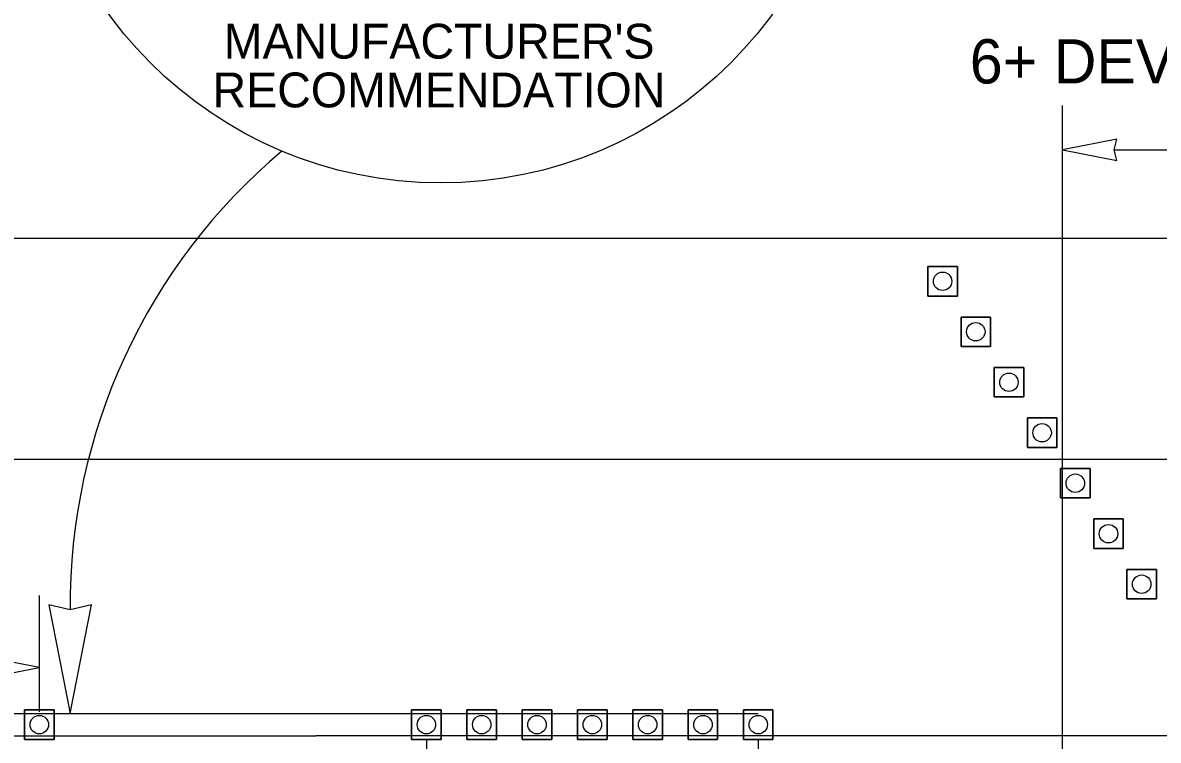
# Model space of a CAD drawing. Extents: x 99999.1 to 100095.7, y 99995 to 100010.7.
# Drawn here: x 100042.947 to 100045, y 100006.584 to 100007.882 of the extents above; entities that cross this region are included whole.
import ezdxf

# ---------------------------------------------------------------- set-up
doc = ezdxf.new("R2010")
doc.units = 0
for name, color, linetype in [('RD_ED_ShoulderPavedEdge', 7, 'Continuous'), ('RD_MK_LineDblYellowCenter', 7, 'Continuous'), ('RD_MK_LineEdgeWhite', 7, 'Continuous'), ('RD_MK_LineNoPass', 7, 'Continuous'), ('RD_MK_LineSkipCenter', 7, 'Continuous'), ('TR_WZ_TrafficCone', 7, 'Continuous'), ('TR_WZ_WorkZoneDetails', 7, 'Continuous'), ('TR_WZ_WorkZoneTextCurrent', 7, 'Continuous')]:
    doc.layers.add(name, color=color, linetype=linetype)

msp = doc.modelspace()

# ---------------------------------------------------------------- linework, layer by layer
at = {"layer": 'RD_ED_ShoulderPavedEdge'}
msp.add_line((100040.1076, 100007.4923), (100055.6424, 100007.4923), dxfattribs=at)
at = {"layer": 'RD_MK_LineDblYellowCenter'}
for p, q in [((100040.1282, 100006.6323), (100043.4767, 100006.6323)), ((100040.0869, 100006.5923), (100043.4767, 100006.5923))]:
    msp.add_line(p, q, dxfattribs=at)
at = {"layer": 'RD_MK_LineEdgeWhite'}
msp.add_line((100040.1076, 100007.0923), (100055.6424, 100007.0923), dxfattribs=at)
at = {"layer": 'RD_MK_LineNoPass'}
msp.add_line((100043.4767, 100006.6323), (100044.2767, 100006.6323), dxfattribs=at)
at = {"layer": 'RD_MK_LineSkipCenter'}
msp.add_lwpolyline([(100051.15, 100006.5923), (100043.4767, 100006.5923)], dxfattribs=at)
at = {"layer": 'TR_WZ_TrafficCone'}
for points in [[(100044.6367, 100007.4411), (100044.5834, 100007.4411), (100044.5834, 100007.3877), (100044.6367, 100007.3877), (100044.6367, 100007.4411)], [(100044.6367, 100007.3877), (100044.5834, 100007.3877), (100044.5834, 100007.4411), (100044.6367, 100007.4411), (100044.6367, 100007.3877)], [(100044.6967, 100007.3497), (100044.6434, 100007.3497), (100044.6434, 100007.2964), (100044.6967, 100007.2964), (100044.6967, 100007.3497)], [(100044.6967, 100007.2964), (100044.6434, 100007.2964), (100044.6434, 100007.3497), (100044.6967, 100007.3497), (100044.6967, 100007.2964)], [(100044.7567, 100007.2584), (100044.7034, 100007.2584), (100044.7034, 100007.2051), (100044.7567, 100007.2051), (100044.7567, 100007.2584)], [(100044.7567, 100007.2051), (100044.7034, 100007.2051), (100044.7034, 100007.2584), (100044.7567, 100007.2584), (100044.7567, 100007.2051)], [(100044.8167, 100007.1671), (100044.7634, 100007.1671), (100044.7634, 100007.1137), (100044.8167, 100007.1137), (100044.8167, 100007.1671)], [(100044.8167, 100007.1137), (100044.7634, 100007.1137), (100044.7634, 100007.1671), (100044.8167, 100007.1671), (100044.8167, 100007.1137)], [(100044.8234, 100007.0757), (100044.8767, 100007.0757), (100044.8767, 100007.0224), (100044.8234, 100007.0224), (100044.8234, 100007.0757)], [(100044.8234, 100007.0224), (100044.8767, 100007.0224), (100044.8767, 100007.0757), (100044.8234, 100007.0757), (100044.8234, 100007.0224)], [(100044.8834, 100006.9844), (100044.9367, 100006.9844), (100044.9367, 100006.9311), (100044.8834, 100006.9311), (100044.8834, 100006.9844)], [(100044.8834, 100006.9311), (100044.9367, 100006.9311), (100044.9367, 100006.9844), (100044.8834, 100006.9844), (100044.8834, 100006.9311)], [(100044.9434, 100006.8931), (100044.9967, 100006.8931), (100044.9967, 100006.8397), (100044.9434, 100006.8397), (100044.9434, 100006.8931)], [(100044.9434, 100006.8397), (100044.9967, 100006.8397), (100044.9967, 100006.8931), (100044.9434, 100006.8931), (100044.9434, 100006.8397)], [(100043.0033, 100006.639), (100042.95, 100006.639), (100042.95, 100006.5857), (100043.0033, 100006.5857), (100043.0033, 100006.639)], [(100043.0033, 100006.5857), (100042.95, 100006.5857), (100042.95, 100006.639), (100043.0033, 100006.639), (100043.0033, 100006.5857)], [(100043.7033, 100006.639), (100043.65, 100006.639), (100043.65, 100006.5857), (100043.7033, 100006.5857), (100043.7033, 100006.639)], [(100043.7033, 100006.5857), (100043.65, 100006.5857), (100043.65, 100006.639), (100043.7033, 100006.639), (100043.7033, 100006.5857)], [(100043.8033, 100006.639), (100043.75, 100006.639), (100043.75, 100006.5857), (100043.8033, 100006.5857), (100043.8033, 100006.639)], [(100043.8033, 100006.5857), (100043.75, 100006.5857), (100043.75, 100006.639), (100043.8033, 100006.639), (100043.8033, 100006.5857)], [(100043.9033, 100006.639), (100043.85, 100006.639), (100043.85, 100006.5857), (100043.9033, 100006.5857), (100043.9033, 100006.639)], [(100043.9033, 100006.5857), (100043.85, 100006.5857), (100043.85, 100006.639), (100043.9033, 100006.639), (100043.9033, 100006.5857)], [(100044.0033, 100006.639), (100043.95, 100006.639), (100043.95, 100006.5857), (100044.0033, 100006.5857), (100044.0033, 100006.639)], [(100044.0033, 100006.5857), (100043.95, 100006.5857), (100043.95, 100006.639), (100044.0033, 100006.639), (100044.0033, 100006.5857)], [(100044.1033, 100006.639), (100044.05, 100006.639), (100044.05, 100006.5857), (100044.1033, 100006.5857), (100044.1033, 100006.639)], [(100044.1033, 100006.5857), (100044.05, 100006.5857), (100044.05, 100006.639), (100044.1033, 100006.639), (100044.1033, 100006.5857)], [(100044.2033, 100006.639), (100044.15, 100006.639), (100044.15, 100006.5857), (100044.2033, 100006.5857), (100044.2033, 100006.639)], [(100044.2033, 100006.5857), (100044.15, 100006.5857), (100044.15, 100006.639), (100044.2033, 100006.639), (100044.2033, 100006.5857)], [(100044.3033, 100006.639), (100044.25, 100006.639), (100044.25, 100006.5857), (100044.3033, 100006.5857), (100044.3033, 100006.639)], [(100044.3033, 100006.5857), (100044.25, 100006.5857), (100044.25, 100006.639), (100044.3033, 100006.639), (100044.3033, 100006.5857)]]:
    msp.add_lwpolyline(points, dxfattribs=at)
for centre in [(100044.61, 100007.4144), (100044.67, 100007.3231), (100044.73, 100007.2317), (100044.79, 100007.1404), (100044.85, 100007.0491), (100044.91, 100006.9577), (100044.97, 100006.8664), (100042.9767, 100006.6123), (100043.6767, 100006.6123), (100043.7767, 100006.6123), (100043.8767, 100006.6123), (100043.9767, 100006.6123), (100044.0767, 100006.6123), (100044.1767, 100006.6123), (100044.2767, 100006.6123)]:
    msp.add_circle(centre, 0.0167, dxfattribs=at)
at = {"layer": 'TR_WZ_WorkZoneDetails'}
for p, q in [((100044.8267, 100005.7523), (100044.8267, 100007.7323)), ((100044.9204, 100007.6523), (100045.0563, 100007.6523)), ((100042.9767, 100006.8457), (100042.9767, 100006.6357)), ((100043.6767, 100006.5857), (100043.6767, 100006.4023)), ((100044.2767, 100006.5857), (100044.2767, 100006.4023))]:
    msp.add_line(p, q, dxfattribs=at)
for points in [[(100044.8267, 100007.6523), (100044.9249, 100007.6331), (100044.9204, 100007.6523), (100044.9249, 100007.6716)], [(100043.0323, 100006.6323), (100043.0708, 100006.8289), (100043.0323, 100006.8198), (100042.9937, 100006.8289)], [(100042.9767, 100006.7157), (100042.8784, 100006.7349), (100042.8829, 100006.7157), (100042.8784, 100006.6964)]]:
    msp.add_lwpolyline(points, close=True, dxfattribs=at)
msp.add_circle((100043.7022, 100008.3343), 0.742, dxfattribs=at)
msp.add_arc((100044.1081, 100006.8268), 1.0759, 130.0809, 180.3733, dxfattribs=at)

# ---------------------------------------------------------------- texts
for s, p in [("MANUFACTURER'S", (100043.3102, 100007.8172)), ('RECOMMENDATION', (100043.2898, 100007.729))]:
    msp.add_text(s, height=0.063, dxfattribs=at).set_placement(p)
at = {"layer": 'TR_WZ_WorkZoneTextCurrent'}
msp.add_text('6+ DEVICES', height=0.08, rotation=360, dxfattribs=at).set_placement((100044.6592, 100007.7723))

doc.saveas('drawing.dxf')
